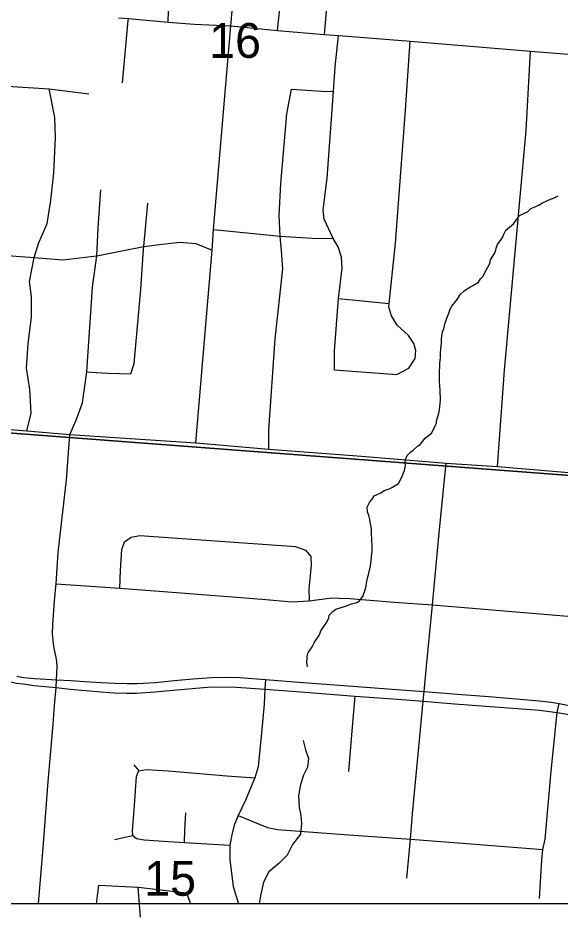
# Model space of a CAD drawing. Extents: x 0 to 34, y 0 to 22.
# Drawn here: x 18.928 to 19.579, y 16.438 to 17.53 of the extents above; entities that cross this region are included whole.
import ezdxf

# ---------------------------------------------------------------- set-up
doc = ezdxf.new("R2010")
doc.units = 0
for name, color, linetype in [('GM_X_City_Street', 7, 'Continuous'), ('GM_X_County_Road', 7, 'Continuous'), ('GM_X_Minor_River', 7, 'Continuous'), ('GM_X_Section', 7, 'Continuous'), ('GM_X_Section_Text', 7, 'Continuous'), ('GM_X_State_Route', 7, 'Continuous'), ('SH_Text', 7, 'Continuous')]:
    doc.layers.add(name, color=color, linetype=linetype)

msp = doc.modelspace()

# ---------------------------------------------------------------- linework, layer by layer
at = {"layer": 'GM_X_City_Street'}
for p, q in [((19.3122, 17.1931), (19.3732, 17.1873)), ((19.3073, 17.1077), (19.3824, 17.1019)), ((18.9858, 16.9806), (18.9894, 17.0299)), ((19.0217, 16.4662), (19.0242, 16.4886)), ((19.0744, 16.4504), (19.0717, 16.4862))]:
    msp.add_line(p, q, dxfattribs=at)
for points in [[(19.1076, 17.5253), (19.1083, 17.5528), (19.1134, 17.5966), (19.1145, 17.6106), (19.1123, 17.6517), (19.108, 17.6854), (19.0986, 17.714)], [(19.1409, 17.0198), (19.1551, 17.1902), (19.1603, 17.2512), (19.1622, 17.2762), (19.183, 17.5207), (19.1866, 17.5615), (19.189, 17.5903), (19.1916, 17.6028), (19.1887, 17.6223), (19.184, 17.6441), (19.1796, 17.6499), (19.1529, 17.7079)], [(19.2388, 17.515), (19.2429, 17.5533), (19.2463, 17.5843), (19.2459, 17.6116), (19.2434, 17.6314), (19.24, 17.6442), (19.2349, 17.6726), (19.228, 17.6887), (19.212, 17.7103)], [(19.2955, 17.5105), (19.2989, 17.5526), (19.3017, 17.5796), (19.3077, 17.6349), (19.3126, 17.7038)], [(18.3788, 17.5289), (18.4032, 17.5088), (18.422, 17.4901), (18.423, 17.4896), (18.4387, 17.4824), (18.4697, 17.4749), (18.5072, 17.4747), (18.5406, 17.4871), (18.5734, 17.4962), (18.6022, 17.4953), (18.6242, 17.4898), (18.6492, 17.4842), (18.695, 17.4698), (18.7468, 17.4612), (18.7814, 17.458), (18.8249, 17.4554), (18.87, 17.4509), (18.9648, 17.4452), (19.0125, 17.4391)], [(19.053, 17.4524), (19.0595, 17.5273), (19.0599, 17.5294)], [(19.3073, 17.1077), (19.3075, 17.1305), (19.3122, 17.1931), (19.3166, 17.2298), (19.3158, 17.2428), (19.312, 17.2554), (19.3057, 17.2652), (19.2949, 17.2885), (19.2939, 17.2996), (19.2988, 17.3378), (19.3064, 17.442), (19.3082, 17.4714), (19.3123, 17.5092)], [(19.373, 17.1815), (19.3728, 17.1824), (19.3732, 17.1873), (19.3805, 17.2598), (19.3928, 17.4195), (19.3982, 17.5023)], [(19.5033, 16.9914), (19.5114, 17.1074), (19.5377, 17.3949), (19.5428, 17.4904)], [(18.9381, 17.0344), (18.9432, 17.0557), (18.9417, 17.0842), (18.9376, 17.1098), (18.9397, 17.1394), (18.9436, 17.1708), (18.9435, 17.1955), (18.941, 17.2136), (18.9467, 17.2424), (18.9519, 17.2595), (18.9625, 17.2835), (18.9667, 17.3109), (18.9703, 17.3443), (18.9722, 17.3868), (18.9717, 17.4107), (18.9648, 17.4452)], [(19.2284, 17.0123), (19.2286, 17.035), (19.2363, 17.1448), (19.2455, 17.229), (19.2436, 17.2509), (19.2422, 17.2683), (19.2409, 17.2931), (19.2429, 17.3314), (19.2501, 17.4151), (19.2558, 17.4447)], [(19.2558, 17.4447), (19.2917, 17.4424), (19.3064, 17.442)], [(18.9894, 17.0299), (18.9971, 17.0473), (19.0048, 17.068), (19.0098, 17.1054), (19.0168, 17.2071), (19.022, 17.2447), (19.0235, 17.2782), (19.0266, 17.3239)], [(19.0627, 17.1028), (19.0668, 17.1153), (19.0749, 17.204), (19.0776, 17.2465), (19.0784, 17.2557), (19.0834, 17.3079)], [(18.4, 17.2741), (18.402, 17.2739), (18.4079, 17.2734), (18.4364, 17.27), (18.4988, 17.2648), (18.5938, 17.2541), (18.6337, 17.2501), (18.6734, 17.2464), (18.7285, 17.2421), (18.7533, 17.2396), (18.8095, 17.2444), (18.8697, 17.2484), (18.9091, 17.2452), (18.9467, 17.2424), (18.9812, 17.2398), (19.022, 17.2447), (19.0502, 17.2502), (19.0784, 17.2557), (19.1003, 17.2587), (19.1216, 17.2611), (19.1408, 17.2593), (19.1603, 17.2512)], [(19.1622, 17.2762), (19.2422, 17.2683), (19.2807, 17.2659), (19.3057, 17.2652)], [(19.3824, 17.1019), (19.3966, 17.1096), (19.4041, 17.1214), (19.4052, 17.131), (19.4028, 17.1391), (19.3962, 17.1487), (19.3828, 17.1612), (19.3759, 17.1724), (19.3733, 17.1806), (19.373, 17.1815)], [(19.0098, 17.1054), (19.0212, 17.1046), (19.0357, 17.1038), (19.0627, 17.1028)], [(19.3941, 16.497), (19.3985, 16.544), (19.4011, 16.5745), (19.4087, 16.6544), (19.4138, 16.7097), (19.415, 16.7213), (19.4179, 16.7516), (19.4249, 16.8256), (19.433, 16.9119), (19.4415, 16.9954)], [(18.9723, 16.8431), (18.973, 16.8507), (18.9755, 16.8882), (18.9854, 16.9756), (18.9858, 16.9806)], [(19.0496, 16.8453), (19.0503, 16.867), (19.0519, 16.8919), (19.0553, 16.9012), (19.0633, 16.9067), (19.0738, 16.9086), (19.2607, 16.8953), (19.2724, 16.8912), (19.279, 16.8834), (19.2793, 16.8727), (19.2764, 16.8445), (19.277, 16.8303)], [(18.973, 16.8507), (19.0496, 16.8453), (19.1175, 16.8401), (19.2206, 16.8321), (19.2562, 16.829), (19.277, 16.8303), (19.3042, 16.8337), (19.3125, 16.8334)], [(18.952, 16.4662), (18.958, 16.5387), (18.9637, 16.6131), (18.9664, 16.6451), (18.9696, 16.6821), (18.9711, 16.7047), (18.973, 16.7262), (18.9736, 16.7353), (18.9744, 16.7515), (18.9741, 16.7574), (18.9732, 16.7622), (18.9711, 16.7714), (18.9698, 16.7787), (18.9688, 16.7908), (18.9691, 16.8023), (18.971, 16.8299), (18.9723, 16.8431)], [(19.3125, 16.8334), (19.3258, 16.8329), (19.3791, 16.8285), (19.4249, 16.8256), (19.6214, 16.8091), (19.6451, 16.807), (19.6701, 16.8041), (19.7092, 16.802), (19.7315, 16.7992)], [(19.2245, 16.7358), (19.2239, 16.7243), (19.223, 16.7062), (19.2196, 16.6717), (19.2157, 16.631), (19.2116, 16.6175), (19.2007, 16.5909), (19.1916, 16.5725), (19.1869, 16.5608), (19.1841, 16.5491), (19.1817, 16.5369), (19.1816, 16.5197), (19.1859, 16.487), (19.1921, 16.4662)], [(19.3248, 16.6251), (19.329, 16.6788), (19.3322, 16.7159)], [(19.5536, 16.4728), (19.5565, 16.5188), (19.5577, 16.5317), (19.5603, 16.544), (19.5678, 16.6258), (19.575, 16.6961), (19.5773, 16.707)], [(19.0653, 16.5485), (19.065, 16.5536), (19.0671, 16.5843), (19.0698, 16.6196), (19.0724, 16.626)], [(19.0664, 16.6333), (19.0724, 16.626), (19.0813, 16.6276), (19.1076, 16.6259), (19.1783, 16.62), (19.2116, 16.6175)], [(19.1272, 16.5401), (19.1278, 16.5548), (19.129, 16.5756)], [(19.1916, 16.5725), (19.2162, 16.5625), (19.2268, 16.5582), (19.2391, 16.5558), (19.3189, 16.5498), (19.3985, 16.544), (19.4558, 16.5397), (19.5577, 16.5317)], [(19.0432, 16.5437), (19.0653, 16.5485), (19.0698, 16.5447), (19.0788, 16.5433), (19.1082, 16.5413), (19.1272, 16.5401), (19.1817, 16.5369)], [(19.0242, 16.4886), (19.0717, 16.4862), (19.1298, 16.4796), (19.1344, 16.4662)]]:
    msp.add_lwpolyline(points, dxfattribs=at)
at = {"layer": 'GM_X_County_Road'}
for points in [[(19.0479, 17.5304), (19.0599, 17.5294), (19.1076, 17.5253), (19.139, 17.5226), (19.183, 17.5207), (19.2388, 17.515), (19.2955, 17.5105), (19.3123, 17.5092), (19.3435, 17.5068), (19.3982, 17.5023), (19.5428, 17.4904), (19.5934, 17.4862), (19.5964, 17.4859), (19.6509, 17.4812), (19.682, 17.4786), (19.7019, 17.4727), (19.7261, 17.4662), (19.7441, 17.4582)], [(18.6549, 17.0554), (18.6559, 17.0553), (18.6981, 17.0509), (18.751, 17.0483), (18.8588, 17.0408), (18.9381, 17.0344), (18.9894, 17.0299), (19.1409, 17.0198), (19.2284, 17.0123), (19.3398, 17.0039), (19.4415, 16.9954), (19.5033, 16.9914), (19.6075, 16.9829), (19.6303, 16.9803), (19.6815, 16.9757)]]:
    msp.add_lwpolyline(points, dxfattribs=at)
at = {"layer": 'GM_X_Minor_River'}
for points in [[(19.4946, 17.2399), (19.4995, 17.2474), (19.5011, 17.2512), (19.5015, 17.2539), (19.503, 17.258), (19.5076, 17.2641), (19.5095, 17.2674), (19.5107, 17.2705), (19.513, 17.2754), (19.5225, 17.2829), (19.5255, 17.2874), (19.5297, 17.293), (19.5392, 17.2975), (19.543, 17.3013), (19.5491, 17.3039), (19.5533, 17.3057), (19.5571, 17.308), (19.5669, 17.3124), (19.5704, 17.3139), (19.576, 17.3165)], [(19.275, 16.7508), (19.2747, 16.7535), (19.2743, 16.7569), (19.2748, 16.766), (19.2763, 16.7686), (19.2798, 16.7739), (19.2813, 16.7766), (19.2832, 16.7807), (19.2863, 16.7845), (19.2893, 16.7894), (19.2909, 16.7943), (19.2981, 16.8048), (19.3008, 16.8098), (19.3012, 16.8132), (19.3054, 16.8173), (19.3092, 16.8203), (19.3206, 16.824), (19.3278, 16.8266), (19.3342, 16.8284), (19.3376, 16.8303), (19.3415, 16.8355), (19.3446, 16.8446), (19.3453, 16.8484), (19.3457, 16.8514), (19.3473, 16.859), (19.3481, 16.8616), (19.3492, 16.8651), (19.3508, 16.8722), (19.3516, 16.8791), (19.3521, 16.8866), (19.3525, 16.8904), (19.3525, 16.8965), (19.3522, 16.9029), (19.3519, 16.9117), (19.3519, 16.9151), (19.3515, 16.9193), (19.3504, 16.9246), (19.3497, 16.928), (19.3486, 16.9326), (19.3471, 16.9371), (19.3468, 16.9428), (19.3499, 16.9492), (19.3525, 16.9522), (19.3552, 16.9564), (19.3632, 16.9601), (19.367, 16.9627), (19.3742, 16.9653), (19.3772, 16.9668), (19.3844, 16.9713), (19.3883, 16.9788), (19.3902, 16.9841), (19.3914, 16.9868), (19.3925, 16.9928), (19.3922, 16.9966), (19.3926, 17), (19.3945, 17.0046), (19.3987, 17.0087), (19.4017, 17.0113), (19.4071, 17.0158), (19.4101, 17.0181), (19.4162, 17.0256), (19.4238, 17.0316), (19.4265, 17.0358), (19.4284, 17.0403), (19.43, 17.0437), (19.43, 17.0463), (19.4319, 17.0528), (19.4327, 17.0554), (19.4335, 17.0592), (19.4347, 17.0717), (19.4347, 17.0755), (19.4344, 17.0785), (19.4344, 17.0827), (19.4334, 17.0941), (19.4334, 17.1021), (19.4339, 17.1153), (19.4347, 17.1225), (19.4347, 17.1271), (19.4352, 17.1328), (19.436, 17.1396), (19.436, 17.1449), (19.4372, 17.1532), (19.4387, 17.157), (19.4399, 17.163), (19.443, 17.1717), (19.4449, 17.1755), (19.4465, 17.1804), (19.4484, 17.1842), (19.4537, 17.1906), (19.4556, 17.1932), (19.4583, 17.1981), (19.4629, 17.2019), (19.4667, 17.2049), (19.4709, 17.2075), (19.4735, 17.209), (19.4804, 17.2131), (19.4827, 17.2169), (19.4857, 17.2199), (19.4899, 17.2282), (19.4938, 17.2354), (19.4946, 17.2399)], [(19.2696, 16.6627), (19.2727, 16.6512), (19.2762, 16.6409), (19.2748, 16.6306), (19.2703, 16.6209), (19.2666, 16.6096), (19.2643, 16.5959), (19.265, 16.5822), (19.267, 16.5723), (19.2679, 16.5627), (19.2664, 16.5502), (19.2569, 16.5376), (19.2504, 16.5248), (19.2406, 16.5148), (19.2286, 16.5049), (19.2221, 16.4925), (19.2186, 16.4759), (19.2168, 16.4662)]]:
    msp.add_lwpolyline(points, dxfattribs=at)
at = {"layer": 'GM_X_Section'}
for points in [[(18.7361, 18.0659), (19.771, 17.9818), (19.6906, 16.9733), (18.6301, 17.0536)], [(18.6301, 17.0536), (19.6906, 16.9733), (19.5996, 15.976), (18.5443, 16.0316)]]:
    msp.add_lwpolyline(points, close=True, dxfattribs=at)
at = {"layer": 'GM_X_State_Route'}
for points in [[(18.4071, 16.8919), (18.4267, 16.8886), (18.4539, 16.8857), (18.4841, 16.8825), (18.5146, 16.8794), (18.537, 16.877), (18.5505, 16.8754), (18.5623, 16.8731), (18.5747, 16.8701), (18.5891, 16.8657), (18.6123, 16.8568), (18.6375, 16.8463), (18.6598, 16.8369), (18.7013, 16.8197), (18.7501, 16.7994), (18.7987, 16.779), (18.8539, 16.7559), (18.8892, 16.7415), (18.9035, 16.7367), (18.9178, 16.733), (18.9257, 16.7313), (18.9331, 16.7304), (18.9468, 16.7287), (18.973, 16.7262)], [(18.9258, 16.7396), (18.9341, 16.7383), (18.9474, 16.7369), (18.9736, 16.7353), (18.9906, 16.7345), (19.0076, 16.7334), (19.0272, 16.7323), (19.0435, 16.7314), (19.0583, 16.7309), (19.0701, 16.731), (19.0924, 16.7323), (19.1149, 16.7347), (19.1373, 16.7367), (19.1597, 16.7383), (19.1763, 16.7386), (19.1937, 16.7382), (19.2245, 16.7358), (19.2595, 16.7331), (19.2969, 16.7303), (19.3345, 16.7273), (19.3873, 16.7234), (19.415, 16.7213), (19.455, 16.7181), (19.4926, 16.7152), (19.5305, 16.7122), (19.5533, 16.7102), (19.5675, 16.7087), (19.5773, 16.707), (19.5976, 16.7028)], [(18.973, 16.7262), (18.9901, 16.7242), (19.0087, 16.7224), (19.0266, 16.7208), (19.0425, 16.7197), (19.0577, 16.7193), (19.0695, 16.7195), (19.0918, 16.7208), (19.1138, 16.7228), (19.1363, 16.7249), (19.1591, 16.7268), (19.1892, 16.7266), (19.2239, 16.7243), (19.2566, 16.7218), (19.2868, 16.7195), (19.3322, 16.7159), (19.3831, 16.7122), (19.4138, 16.7097), (19.4519, 16.7065), (19.4893, 16.7037), (19.5266, 16.7009), (19.5537, 16.6989), (19.575, 16.6961), (19.6157, 16.6895)]]:
    msp.add_lwpolyline(points, dxfattribs=at)
at = {"layer": 'SH_Text'}
msp.add_lwpolyline([(19.5901, 16.4662), (17.6011, 16.4662), (17.6011, 16.0631), (19.5901, 16.0631), (19.5901, 16.1639), (20.4399, 16.63), (19.5901, 16.2646)], close=True, dxfattribs=at)

# ---------------------------------------------------------------- texts
at = {"layer": 'GM_X_Section_Text'}
for s, p in [('16', (19.1569, 17.4822)), ('15', (19.0789, 16.4761))]:
    msp.add_text(s, height=0.04186, rotation=0, dxfattribs=at).set_placement(p)

doc.saveas('drawing.dxf')
